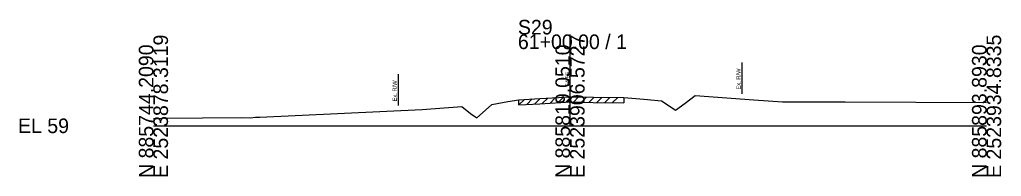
# Model space of a CAD drawing. Extents: x -26 to 163, y -10 to 4024.
# Drawn here: x -25.7 to 162.8, y 1490.3 to 1520.4 of the extents above; entities that cross this region are included whole.
import ezdxf

# ---------------------------------------------------------------- set-up
doc = ezdxf.new("R2010")
doc.units = 0
for name, color, linetype in [('RD_GPK_XS_Cell', 7, 'Continuous'), ('RD_XS_ExGround', 7, 'Continuous'), ('RD_XS_ExPaveRet', 7, 'Continuous'), ('RD_XS_ExRW', 7, 'Continuous'), ('RD_XS_TX_Elev_EX', 7, 'Continuous')]:
    doc.layers.add(name, color=color, linetype=linetype)

msp = doc.modelspace()

# ---------------------------------------------------------------- linework, layer by layer
at = {"layer": 'RD_GPK_XS_Cell'}
for p, q in [((80, 1500), (80, 1517.52)), ((0, 1500), (80, 1500)), ((80, 1500), (160, 1500))]:
    msp.add_line(p, q, dxfattribs=at)
at = {"layer": 'RD_XS_ExGround'}
for p, q in [((64.99, 1504.1), (68.05, 1504.64)), ((68.05, 1504.64), (70.18, 1505.01)), ((70.18, 1505.01), (74.2, 1505.24)), ((74.2, 1505.24), (80.18, 1505.57)), ((80.18, 1505.57), (84.44, 1505.5)), ((84.44, 1505.5), (90.33, 1505.42)), ((90.33, 1505.42), (94.16, 1505.1)), ((94.16, 1505.1), (97.57, 1504.82)), ((97.57, 1504.82), (99.05, 1503.8)), ((102.09, 1504.33), (104.05, 1505.84)), ((104.05, 1505.84), (115.32, 1504.99)), ((115.32, 1504.99), (120.81, 1504.58)), ((120.81, 1504.58), (132.83, 1504.6)), ((132.83, 1504.6), (160, 1504.5)), ((20.45, 1501.64), (51.59, 1503.1)), ((51.59, 1503.1), (59.2, 1503.69)), ((59.2, 1503.69), (60.89, 1502.39)), ((62.11, 1501.5), (63.8, 1503.02)), ((63.8, 1503.02), (64.99, 1504.1)), ((99.05, 1503.8), (100.25, 1502.97)), ((100.25, 1502.97), (102.09, 1504.33)), ((0, 1501.4), (0.73, 1501.42)), ((0.73, 1501.42), (1.84, 1501.45)), ((1.84, 1501.45), (16.95, 1501.57)), ((16.95, 1501.57), (18.64, 1501.56)), ((18.64, 1501.56), (19.59, 1501.65)), ((19.59, 1501.65), (20.45, 1501.64)), ((60.89, 1502.39), (62.11, 1501.5))]:
    msp.add_line(p, q, dxfattribs=at)
at = {"layer": 'RD_XS_ExPaveRet'}
for p, q in [((70.18, 1504.01), (71.24, 1505.07)), ((70.18, 1504.01), (70.18, 1505.01)), ((71.68, 1504.1), (72.74, 1505.16)), ((73.18, 1504.18), (74.24, 1505.25)), ((74.2, 1504.24), (80.18, 1504.57)), ((74.68, 1504.27), (75.74, 1505.33)), ((76.18, 1504.35), (77.24, 1505.41)), ((77.68, 1504.43), (78.74, 1505.49)), ((79.18, 1504.51), (80.23, 1505.57)), ((80.18, 1504.57), (84.44, 1504.5)), ((80.68, 1504.56), (81.66, 1505.54)), ((82.18, 1504.54), (83.16, 1505.52)), ((83.68, 1504.51), (84.66, 1505.5)), ((84.44, 1504.5), (90.33, 1504.42)), ((85.18, 1504.49), (86.17, 1505.48)), ((86.68, 1504.47), (87.67, 1505.46)), ((88.18, 1504.45), (89.17, 1505.44)), ((90.33, 1505.42), (90.33, 1504.42)), ((70.18, 1504.01), (74.2, 1504.24))]:
    msp.add_line(p, q, dxfattribs=at)
at = {"layer": 'RD_XS_ExRW'}
for p, q in [((113, 1512.16), (113, 1506.16)), ((47, 1509.88), (47, 1503.88))]:
    msp.add_line(p, q, dxfattribs=at)

# ---------------------------------------------------------------- texts
at = {"layer": 'RD_GPK_XS_Cell'}
for s, p in [('S29', (70, 1517.52)), ('61+00.00 / 1', (70, 1514.72)), ('EL 59', (-26, 1498.6))]:
    msp.add_text(s, height=2.8, dxfattribs=at).set_placement(p)
for s, p in [('E 2523878.3119', (2.8, 1490)), ('E 2523906.5727', (82.8, 1490)), ('E 2523934.8335', (162.8, 1490)), ('N 885744.2090', (0, 1490)), ('N 885819.0510', (80, 1490)), ('N 885893.8930', (160, 1490))]:
    msp.add_text(s, height=2.8, rotation=90, dxfattribs=at).set_placement(p)
at = {"layer": 'RD_XS_ExRW'}
for p in [(112.75, 1506.95), (46.75, 1504.67)]:
    msp.add_text('Ex. R/W ', height=0.8, rotation=90, dxfattribs=at).set_placement(p)
at = {"layer": 'RD_XS_TX_Elev_EX'}
msp.add_text('64.56', height=0.8, rotation=90, dxfattribs=at).set_placement((79.9, 1507.56))

doc.saveas('drawing.dxf')
